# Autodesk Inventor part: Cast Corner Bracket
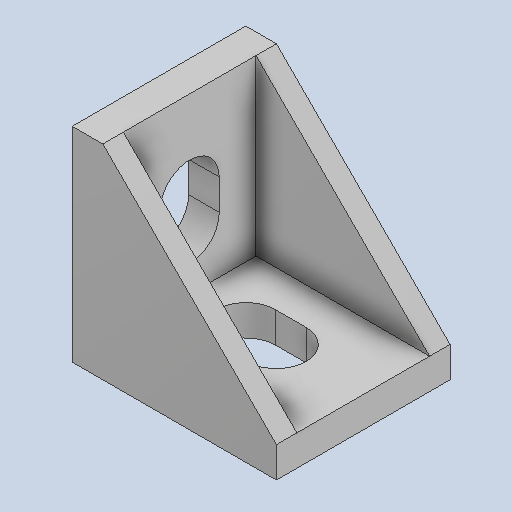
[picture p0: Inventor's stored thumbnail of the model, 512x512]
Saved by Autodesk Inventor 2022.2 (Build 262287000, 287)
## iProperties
Created: 2019-09
Part Number: Cast Corner Bracket
Material: SolidWorks Materials|6061-T6 (SS)
Document SubType Name: Modeling
Designer: 18907419
Density: 2.7 g/cm^3
Appearance: Default
Author: 18907419
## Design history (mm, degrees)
feature "Solido1"
node "Solido2"
